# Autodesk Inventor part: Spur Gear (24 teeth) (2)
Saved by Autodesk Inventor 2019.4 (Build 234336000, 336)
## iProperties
Created: 2020-02
Part Number: Spur Gear (24 teeth) (2)
Material: Generic
Description: Spur Gear; Module: 1.0; Num Teeth: 24; Pressure Angle: 20.0; Backlash: 0.00 mm
Document SubType Name: Modeling
Designer: Administrator
Density: 1 g/cm^3
Appearance: Default
Title: Spur Gear (24 teeth) (2)
Author: Administrator
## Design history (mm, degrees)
feature "Body1"
body "Solid1"
